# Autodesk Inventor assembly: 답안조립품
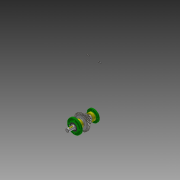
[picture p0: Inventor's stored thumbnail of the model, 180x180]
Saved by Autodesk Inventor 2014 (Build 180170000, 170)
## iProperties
Created: 2016-12
Part Number: 답안조립품
Document SubType Name: Assembly
Designer: owner
Author: owner
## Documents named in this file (15)
- C:\Users\owner\Desktop\461207V1019\답안조립품.iam
- C:\Users\owner\Desktop\461207V1019\본체.ipt
- C:\Users\owner\Desktop\461207V1019\키 - 6 x 6 x 22.ipt
- C:\Users\owner\Desktop\461207V1019\키 - 5 x 5 x 18.ipt
- C:\Users\owner\Desktop\461207V1019\축.ipt
- C:\Users\owner\Desktop\461207V1019\오일씰 28 40 8.ipt
- C:\Users\owner\Desktop\461207V1019\앞커버.ipt
- C:\Users\owner\Desktop\461207V1019\스퍼기어.ipt
- C:\Users\owner\Desktop\461207V1019\부시.ipt
- C:\Users\owner\Desktop\461207V1019\볼트 M3 x 10.ipt
- C:\Users\owner\Desktop\461207V1019\볼트 M3 x 8.ipt
- C:\Users\owner\Desktop\461207V1019\베어링 6203.ipt
- C:\Users\owner\Desktop\461207V1019\멈춤나사 - M4x10.ipt
- C:\Users\owner\Desktop\461207V1019\뒤커버.ipt
- C:\Users\owner\Desktop\461207V1019\V-벨트풀리.ipt
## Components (3 placed, 3 different names)
1. ISO 4762 M3 x 10:1
2. ISO 4762 M3 x 8:1
3. V-벨트풀리:1
